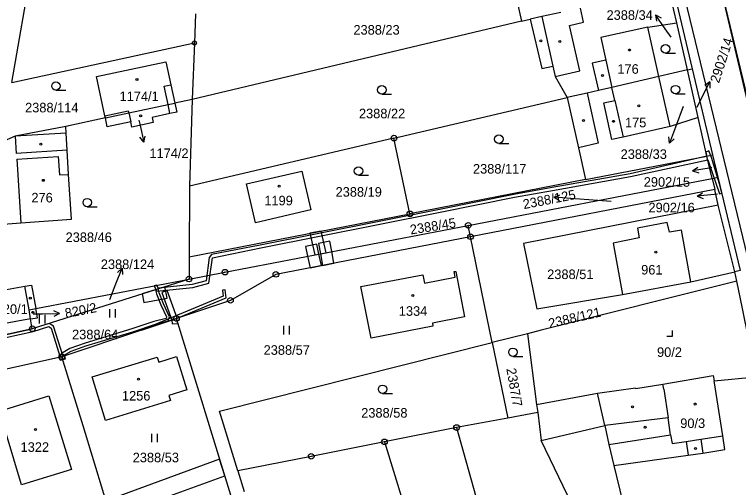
# Model space of a CAD drawing. Extents: x -758836 to -757729, y -1175316 to -1174366.
# Drawn here: x -758454.3 to -758325.7, y -1175111 to -1175027 of the extents above; entities that cross this region are included whole.
import ezdxf

# ---------------------------------------------------------------- set-up
doc = ezdxf.new("R2010")
doc.units = 0
for name, color, linetype in [('Hranice parcel', 7, 'Continuous'), ('Parcelní čísla', 7, 'Continuous'), ('Pop  PČ popisy', 7, 'Continuous'), ('Vnitřní kresba', 7, 'Continuous'), ('Věcná břemena k části', 7, 'Continuous'), ('Značky bodu BP', 7, 'Continuous'), ('Značky budov', 7, 'Continuous'), ('Značky kultur', 7, 'Continuous')]:
    doc.layers.add(name, color=color, linetype=linetype)

msp = doc.modelspace()

# ---------------------------------------------------------------- linework, layer by layer
at = {"layer": 'Hranice parcel'}
for p, q in [((-758367.53, -1175013.58), (-758364.25, -1175028.17)), ((-758336.71, -1175028.44), (-758338.16, -1175021.98)), ((-758422.16, -1175026.87), (-758422.36, -1175032.02)), ((-758364.25, -1175028.17), (-758422.76, -1175042.05)), ((-758364.25, -1175028.17), (-758362.74, -1175027.81)), ((-758334.82, -1175036.8), (-758336.71, -1175028.44)), ((-758454.79, -1175039.02), (-758422.36, -1175032.02)), ((-758422.36, -1175032.02), (-758422.76, -1175042.05)), ((-758334.82, -1175036.8), (-758339.87, -1175037.99)), ((-758334.82, -1175036.8), (-758333.96, -1175036.62)), ((-758332.92, -1175045.26), (-758334.82, -1175036.8)), ((-758333.96, -1175036.62), (-758330.37, -1175051.89)), ((-758422.76, -1175042.05), (-758425.82, -1175042.7)), ((-758422.76, -1175042.05), (-758423.24, -1175057.45)), ((-758386.92, -1175048.94), (-758356.15, -1175041.72)), ((-758438.18, -1175045.35), (-758445.21, -1175046.85)), ((-758331.37, -1175052.13), (-758332.92, -1175045.26)), ((-758386.92, -1175048.94), (-758423.24, -1175057.45)), ((-758384.09, -1175062.4), (-758386.92, -1175048.94)), ((-758352.88, -1175056.32), (-758331.37, -1175052.13)), ((-758331.37, -1175052.13), (-758330.37, -1175051.89)), ((-758330.41, -1175056.09), (-758331.37, -1175052.13)), ((-758330.37, -1175051.89), (-758329.39, -1175055.87)), ((-758352.88, -1175056.32), (-758384.09, -1175062.4)), ((-758330.41, -1175056.09), (-758329.39, -1175055.87)), ((-758330.41, -1175056.09), (-758329.96, -1175058.06)), ((-758329.39, -1175055.87), (-758325.44, -1175072.46)), ((-758423.24, -1175057.45), (-758423.3, -1175070.03)), ((-758329.96, -1175058.06), (-758373.32, -1175066.46)), ((-758329.33, -1175060.85), (-758329.96, -1175058.06)), ((-758326.41, -1175072.69), (-758329.33, -1175060.85)), ((-758423.3, -1175070.03), (-758384.09, -1175062.4)), ((-758373.32, -1175066.46), (-758373.73, -1175064.44)), ((-758373.32, -1175066.46), (-758407.89, -1175073.16)), ((-758369.46, -1175085.29), (-758373.32, -1175066.46)), ((-758423.3, -1175070.03), (-758423.32, -1175073.99)), ((-758334.22, -1175074.5), (-758326.41, -1175072.69)), ((-758325.44, -1175072.46), (-758326.41, -1175072.69)), ((-758326.01, -1175074.36), (-758326.41, -1175072.69)), ((-758423.32, -1175073.99), (-758451.15, -1175082.83)), ((-758450.52, -1175079.23), (-758423.32, -1175073.99)), ((-758346.32, -1175076.76), (-758334.22, -1175074.5)), ((-758451.15, -1175082.83), (-758451.45, -1175081.08)), ((-758415.92, -1175112.41), (-758425.55, -1175080.99)), ((-758363.2, -1175083.72), (-758369.46, -1175085.29)), ((-758363.2, -1175083.72), (-758361.58, -1175096.29)), ((-758369.46, -1175085.29), (-758366.71, -1175098.73)), ((-758445.89, -1175087.81), (-758470.38, -1175093.24)), ((-758330.03, -1175092.1), (-758322.58, -1175091.33)), ((-758361.58, -1175096.29), (-758361.4, -1175097.7)), ((-758366.71, -1175098.73), (-758375.8, -1175100.38)), ((-758361.4, -1175097.7), (-758366.71, -1175098.73)), ((-758361.4, -1175097.7), (-758360.76, -1175102.68)), ((-758375.8, -1175100.38), (-758388.61, -1175102.92)), ((-758375.8, -1175100.38), (-758367.83, -1175129.06)), ((-758349.38, -1175126.44), (-758360.76, -1175102.68)), ((-758388.61, -1175102.92), (-758372.81, -1175154.29)), ((-758414.64, -1175108.08), (-758413.52, -1175111.73))]:
    msp.add_line(p, q, dxfattribs=at)
for points in [[(-758297.14, -1175157.07), (-758301.82, -1175137.17), (-758334.58, -1174998.03), (-758360.35, -1174888.27), (-758361.81, -1174882.07)], [(-758354.19, -1174947.79), (-758350.83, -1174962.63), (-758347.5, -1174977.35), (-758344.08, -1174992.47), (-758340.74, -1175007.26), (-758337.45, -1175021.81), (-758333.96, -1175036.62)], [(-758454.79, -1175039.02), (-758451.2, -1175018.23), (-758447.49, -1174998.37), (-758446.54, -1174994.59)], [(-758357.3, -1175026.59), (-758360.67, -1175027.34), (-758362.74, -1175027.81)], [(-758362.74, -1175027.81), (-758360.65, -1175036.59), (-758358.69, -1175036.15), (-758358.27, -1175038), (-758356.15, -1175041.72)], [(-758339.87, -1175037.99), (-758341.86, -1175029.19), (-758336.71, -1175028.44)], [(-758438.18, -1175045.35), (-758438.27, -1175044.95), (-758439.76, -1175038.01), (-758427.42, -1175035.36), (-758426.52, -1175039.47), (-758425.82, -1175042.7)], [(-758339.87, -1175037.99), (-758348.2, -1175039.91), (-758350.61, -1175040.45), (-758352.63, -1175040.93), (-758356.15, -1175041.72)], [(-758332.92, -1175045.26), (-758337.86, -1175046.85), (-758339.87, -1175037.99)], [(-758356.15, -1175041.72), (-758354.15, -1175050.64), (-758352.88, -1175056.32)], [(-758425.82, -1175042.7), (-758425.48, -1175044.3), (-758426.7, -1175044.56), (-758429.86, -1175045.25), (-758429.67, -1175046.18), (-758433.47, -1175046.99), (-758433.67, -1175046.05), (-758437.83, -1175046.94), (-758438.18, -1175045.35)], [(-758438.18, -1175045.35), (-758434.01, -1175044.46), (-758427.04, -1175042.96), (-758425.82, -1175042.7)], [(-758459.42, -1175064.46), (-758453.17, -1175063.97), (-758444.16, -1175063.35), (-758444.71, -1175055.38), (-758444.96, -1175051.07), (-758445.14, -1175048.05), (-758445.21, -1175046.85)], [(-758445.21, -1175046.85), (-758454.19, -1175048.61), (-758456.63, -1175049.65)], [(-758403.26, -1175054.83), (-758401.68, -1175061.71), (-758411.49, -1175063.99), (-758413.09, -1175057.08), (-758403.26, -1175054.83)], [(-758373.73, -1175064.44), (-758333.2, -1175056.63), (-758330.41, -1175056.09)], [(-758329.33, -1175060.85), (-758363.94, -1175067.64), (-758361.54, -1175079.26), (-758346.32, -1175076.76)], [(-758334.22, -1175074.5), (-758335.85, -1175065.28), (-758338.01, -1175065.68), (-758338.4, -1175063.92), (-758343.65, -1175064.93), (-758343.35, -1175066.68), (-758347.97, -1175067.59), (-758346.32, -1175076.76)], [(-758423.32, -1175073.99), (-758416.94, -1175072.76), (-758373.73, -1175064.44)], [(-758407.89, -1175073.16), (-758415.96, -1175077.77), (-758425.55, -1175080.99)], [(-758381.49, -1175074.69), (-758376.03, -1175073.65), (-758376.21, -1175072.67), (-758375.94, -1175072.63), (-758374.37, -1175080.71), (-758380.1, -1175081.81), (-758380, -1175082.36), (-758390.99, -1175084.49), (-758392.78, -1175075.33), (-758381.78, -1175073.21), (-758381.49, -1175074.69)], [(-758326.01, -1175074.36), (-758360.75, -1175083.1), (-758363.2, -1175083.72)], [(-758322.58, -1175091.33), (-758323.49, -1175086.82), (-758324.78, -1175080.41), (-758325.02, -1175079.25), (-758326.01, -1175074.36)], [(-758451.45, -1175081.08), (-758457.34, -1175082.12), (-758458.39, -1175076.34), (-758452.45, -1175075.26), (-758451.28, -1175075.05), (-758450.52, -1175079.23)], [(-758451.45, -1175081.08), (-758451.73, -1175079.46), (-758450.52, -1175079.23)], [(-758451.45, -1175081.08), (-758450.22, -1175080.86), (-758450.52, -1175079.23)], [(-758425.55, -1175080.99), (-758431.74, -1175083.06), (-758445.89, -1175087.81)], [(-758474.49, -1175088.01), (-758463.5, -1175085.57), (-758451.15, -1175082.83)], [(-758414.64, -1175108.08), (-758417.89, -1175097.49), (-758369.46, -1175085.29)], [(-758436.59, -1175118.23), (-758442.14, -1175100.06), (-758445.89, -1175087.81)], [(-758423.72, -1175093.65), (-758426.88, -1175094.66), (-758426.59, -1175095.6), (-758438.18, -1175099.13), (-758440.54, -1175091.38), (-758428.96, -1175087.86), (-758428.67, -1175088.79), (-758425.56, -1175087.78), (-758423.72, -1175093.65)], [(-758361.58, -1175096.29), (-758350.75, -1175094.27), (-758344, -1175093.3), (-758343.97, -1175093.45), (-758339.15, -1175092.67), (-758330.21, -1175091.16), (-758330.03, -1175092.1)], [(-758347.9, -1175107.11), (-758334.65, -1175105.31), (-758332.05, -1175104.91), (-758328.15, -1175104.31), (-758328.53, -1175101.84), (-758330.03, -1175092.1)], [(-758457.04, -1175097.46), (-758448.22, -1175094.76), (-758444.21, -1175107.85), (-758453.04, -1175110.56), (-758457.04, -1175097.46)], [(-758360.76, -1175102.68), (-758349.48, -1175100.04), (-758348.74, -1175103.39), (-758347.9, -1175107.11)], [(-758388.61, -1175102.92), (-758401.62, -1175105.5), (-758414.64, -1175108.08)], [(-758347.9, -1175107.11), (-758343.08, -1175126.87), (-758339.13, -1175132.41)]]:
    msp.add_lwpolyline(points, dxfattribs=at)
at = {"layer": 'Pop  PČ popisy'}
for p, q in [((-758338.75, -1175029.5), (-758340.47, -1175027.04)), ((-758340.47, -1175027.04), (-758339.49, -1175027.57)), ((-758340.47, -1175027.04), (-758340.31, -1175028.15)), ((-758337.67, -1175031.02), (-758338.75, -1175029.5)), ((-758332.17, -1175041.61), (-758330.81, -1175038.94)), ((-758330.81, -1175038.94), (-758331.71, -1175039.6)), ((-758330.81, -1175038.94), (-758330.82, -1175040.06)), ((-758333.09, -1175043.45), (-758332.17, -1175041.61)), ((-758335.57, -1175043.31), (-758336.94, -1175046.99)), ((-758432.21, -1175045.73), (-758431.99, -1175046.72)), ((-758431.99, -1175046.72), (-758431.37, -1175049.66)), ((-758336.94, -1175046.99), (-758337.97, -1175049.81)), ((-758431.37, -1175049.66), (-758431.08, -1175048.57)), ((-758337.97, -1175049.81), (-758338.09, -1175048.7)), ((-758431.37, -1175049.66), (-758432.06, -1175048.78)), ((-758337.97, -1175049.81), (-758337.15, -1175049.04)), ((-758333.88, -1175054.77), (-758332.98, -1175054.1)), ((-758330.92, -1175054.25), (-758333.88, -1175054.77)), ((-758333.88, -1175054.77), (-758332.8, -1175055.09)), ((-758330.49, -1175054.18), (-758330.92, -1175054.25)), ((-758358.5, -1175059.45), (-758357.47, -1175059.02)), ((-758333.05, -1175059.28), (-758332.1, -1175058.68)), ((-758330.06, -1175058.97), (-758333.05, -1175059.28)), ((-758329.48, -1175058.91), (-758330.06, -1175058.97)), ((-758355.51, -1175059.66), (-758358.5, -1175059.45)), ((-758358.5, -1175059.45), (-758357.54, -1175060.02)), ((-758348.36, -1175060.2), (-758355.51, -1175059.66)), ((-758333.05, -1175059.28), (-758332, -1175059.68)), ((-758436.29, -1175074.86), (-758435.22, -1175072.06)), ((-758435.22, -1175072.06), (-758436.04, -1175072.81)), ((-758435.22, -1175072.06), (-758435.11, -1175073.17)), ((-758437.36, -1175077.62), (-758436.29, -1175074.86)), ((-758446.34, -1175080.1), (-758447.35, -1175079.61)), ((-758451.01, -1175080.18), (-758449.34, -1175080.15)), ((-758449.34, -1175080.15), (-758446.34, -1175080.1)), ((-758446.34, -1175080.1), (-758447.33, -1175080.62))]:
    msp.add_line(p, q, dxfattribs=at)
at = {"layer": 'Vnitřní kresba'}
for p, q in [((-758334.58, -1174998.03), (-758301.51, -1175137.25)), ((-758303.3, -1175156.35), (-758341.2, -1174999.31)), ((-758353.24, -1175028.35), (-758353.81, -1175025.81)), ((-758360.67, -1175027.34), (-758358.69, -1175036.15)), ((-758355.72, -1175028.93), (-758353.24, -1175028.35)), ((-758353.89, -1175036.99), (-758355.72, -1175028.93)), ((-758341.86, -1175029.19), (-758350.2, -1175031.07)), ((-758350.2, -1175031.07), (-758349.3, -1175035.06)), ((-758349.3, -1175035.06), (-758351.71, -1175035.6)), ((-758351.71, -1175035.6), (-758350.61, -1175040.45)), ((-758349.3, -1175035.06), (-758348.2, -1175039.91)), ((-758358.27, -1175038), (-758353.89, -1175036.99)), ((-758427.73, -1175039.73), (-758426.52, -1175039.47)), ((-758427.04, -1175042.96), (-758427.73, -1175039.73)), ((-758352.63, -1175040.93), (-758350.65, -1175049.86)), ((-758347.67, -1175042.23), (-758348.2, -1175039.91)), ((-758349.65, -1175042.68), (-758347.67, -1175042.23)), ((-758347.67, -1175042.23), (-758346.2, -1175048.74)), ((-758426.7, -1175044.56), (-758427.04, -1175042.96)), ((-758348.22, -1175049.2), (-758349.65, -1175042.68)), ((-758438.27, -1175044.95), (-758434.1, -1175044.06)), ((-758434.1, -1175044.06), (-758434.01, -1175044.46)), ((-758434.01, -1175044.46), (-758433.67, -1175046.05)), ((-758337.86, -1175046.85), (-758346.2, -1175048.74)), ((-758445.14, -1175048.05), (-758454.19, -1175048.61)), ((-758454.19, -1175048.61), (-758453.99, -1175051.65)), ((-758346.2, -1175048.74), (-758348.22, -1175049.2)), ((-758350.65, -1175049.86), (-758354.15, -1175050.64)), ((-758444.96, -1175051.07), (-758453.99, -1175051.65)), ((-758453.92, -1175052.67), (-758446.56, -1175052.18)), ((-758446.56, -1175052.18), (-758446.32, -1175055.48)), ((-758453.92, -1175052.67), (-758453.17, -1175063.97)), ((-758446.32, -1175055.48), (-758444.71, -1175055.38)), ((-758451.73, -1175079.46), (-758452.45, -1175075.26)), ((-758339, -1175093.56), (-758339.15, -1175092.67)), ((-758339, -1175093.56), (-758338.23, -1175098.67)), ((-758349.48, -1175100.04), (-758350.75, -1175094.27)), ((-758338.23, -1175098.67), (-758349.48, -1175100.04)), ((-758337.8, -1175101.69), (-758338.23, -1175098.67)), ((-758348.74, -1175103.39), (-758337.8, -1175101.69)), ((-758337.8, -1175101.69), (-758337.54, -1175103.22)), ((-758335.03, -1175102.84), (-758332.43, -1175102.44)), ((-758332.43, -1175102.44), (-758328.53, -1175101.84)), ((-758332.43, -1175102.44), (-758332.05, -1175104.91)), ((-758337.54, -1175103.22), (-758335.03, -1175102.84)), ((-758335.03, -1175102.84), (-758334.65, -1175105.31))]:
    msp.add_line(p, q, dxfattribs=at)
at = {"layer": 'Věcná břemena k části'}
for points in [[(-758329.11, -1175058.81), (-758328.72, -1175058.7), (-758329.1, -1175057.07), (-758330.5, -1175052.36), (-758330.98, -1175051.22), (-758331.52, -1175051.45), (-758331.37, -1175052.13), (-758344.99, -1175055.27), (-758358.85, -1175057.73), (-758365.63, -1175058.95), (-758378.83, -1175061.62), (-758389.83, -1175063.8), (-758410.66, -1175067.95), (-758419.34, -1175069.61), (-758419.76, -1175070.15), (-758420.26, -1175074.32), (-758422.74, -1175074.96), (-758428.77, -1175075.62), (-758429.02, -1175075.09), (-758429.52, -1175075.18), (-758429.07, -1175076.16), (-758422.65, -1175075.46), (-758419.8, -1175074.72), (-758419.16, -1175070.2), (-758410.56, -1175068.44), (-758389.73, -1175064.29), (-758378.73, -1175062.11), (-758365.53, -1175059.45), (-758358.77, -1175058.23), (-758344.89, -1175055.76), (-758331.21, -1175052.8)], [(-758398.95, -1175069.3), (-758399.84, -1175065.46), (-758401.84, -1175065.85), (-758400.96, -1175069.68)], [(-758402.61, -1175068.2), (-758402.25, -1175069.93), (-758401.82, -1175071.98), (-758399.82, -1175071.6), (-758400.25, -1175069.55), (-758400.62, -1175067.78)], [(-758400.33, -1175067.65), (-758399.98, -1175069.49), (-758399.59, -1175071.55), (-758397.58, -1175071.16), (-758397.97, -1175069.11), (-758398.32, -1175067.27)], [(-758446.23, -1175087.88), (-758445.89, -1175087.81), (-758445.64, -1175087.73), (-758445.58, -1175087.55), (-758444.27, -1175086.82), (-758441.63, -1175085.86), (-758433.31, -1175083.34), (-758429.44, -1175082.04), (-758427, -1175081.43), (-758426.79, -1175080.69), (-758427.85, -1175078.39), (-758428.62, -1175076.46), (-758428.81, -1175075.73), (-758429.29, -1175075.89), (-758429.1, -1175076.62), (-758428.31, -1175078.59), (-758427.33, -1175080.73), (-758427.4, -1175081.01), (-758429.58, -1175081.56), (-758433.47, -1175082.86), (-758441.79, -1175085.38), (-758444.47, -1175086.36), (-758445.98, -1175087.21)], [(-758427.21, -1175077.39), (-758427.6, -1175075.35), (-758431.65, -1175076.63), (-758431.35, -1175078.18)], [(-758431.74, -1175083.06), (-758425.55, -1175080.99), (-758416.72, -1175077.32), (-758416.88, -1175075.91), (-758417.38, -1175075.96), (-758417.26, -1175077)], [(-758426.38, -1175081.27), (-758425.55, -1175080.99), (-758425.43, -1175080.95), (-758427.2, -1175076.05), (-758428.14, -1175076.39)], [(-758445.89, -1175087.81), (-758445.64, -1175087.73), (-758447.38, -1175082.35), (-758448.16, -1175081.88), (-758451.15, -1175082.83), (-758455.97, -1175083.9), (-758458.7, -1175084.76), (-758473.92, -1175088.73), (-758474.21, -1175088.81), (-758474.05, -1175089.28), (-758473.59, -1175089.16), (-758458.56, -1175085.24), (-758455.84, -1175084.38), (-758451.02, -1175083.31), (-758448.23, -1175082.43), (-758447.8, -1175082.69), (-758446.23, -1175087.88)], [(-758425.28, -1175081.87), (-758425.55, -1175080.99), (-758426.38, -1175081.27), (-758426.32, -1175081.93)], [(-758445.74, -1175088.29), (-758445.89, -1175087.81), (-758446.38, -1175087.92), (-758446.22, -1175088.43)], [(-758445.74, -1175088.29), (-758445.89, -1175087.81), (-758446.23, -1175087.88), (-758446.38, -1175087.92), (-758446.22, -1175088.43)], [(-758445.64, -1175087.73), (-758445.89, -1175087.81), (-758445.74, -1175088.29), (-758445.27, -1175088.14), (-758445.42, -1175087.65)], [(-758445.64, -1175087.73), (-758445.89, -1175087.81), (-758445.74, -1175088.29), (-758445.27, -1175088.14), (-758445.42, -1175087.65)], [(-758456.92, -1175120.55), (-758455.85, -1175123.36), (-758451.64, -1175121.64), (-758437.17, -1175116.34), (-758416.98, -1175108.94), (-758417.89, -1175105.98), (-758438.06, -1175113.43), (-758452.72, -1175118.84)]]:
    msp.add_lwpolyline(points, close=True, dxfattribs=at)
at = {"layer": 'Značky bodu BP'}
for centre, radius in [((-758422.36, -1175032.02), 0.35), ((-758422.36, -1175032.02), 0.0212), ((-758386.92, -1175048.94), 0.5), ((-758386.92, -1175048.94), 0.0303), ((-758384.09, -1175062.4), 0.5), ((-758384.09, -1175062.4), 0.0303), ((-758373.73, -1175064.44), 0.5), ((-758373.73, -1175064.44), 0.0303), ((-758373.32, -1175066.46), 0.5), ((-758373.32, -1175066.46), 0.0303), ((-758416.94, -1175072.76), 0.5), ((-758416.94, -1175072.76), 0.0303), ((-758407.89, -1175073.16), 0.5), ((-758407.89, -1175073.16), 0.0303), ((-758423.32, -1175073.99), 0.5), ((-758423.32, -1175073.99), 0.0303), ((-758415.96, -1175077.77), 0.5), ((-758415.96, -1175077.77), 0.0303), ((-758425.55, -1175080.99), 0.5), ((-758425.55, -1175080.99), 0.0303), ((-758451.15, -1175082.83), 0.5), ((-758451.15, -1175082.83), 0.0303), ((-758445.89, -1175087.81), 0.5), ((-758445.89, -1175087.81), 0.0303), ((-758375.8, -1175100.38), 0.5), ((-758375.8, -1175100.38), 0.0303), ((-758388.61, -1175102.92), 0.5), ((-758388.61, -1175102.92), 0.0303), ((-758401.62, -1175105.5), 0.5), ((-758401.62, -1175105.5), 0.0303)]:
    msp.add_circle(centre, radius, dxfattribs=at)
at = {"layer": 'Značky budov'}
for centre in [(-758360.84, -1175031.64), (-758357.47, -1175031.78), (-758345.07, -1175033.27), (-758432.56, -1175038.51), (-758349.9, -1175037.81), (-758343.44, -1175043.21), (-758431.91, -1175044.97), (-758353.27, -1175045.81), (-758347.94, -1175045.95), (-758449.63, -1175049.99), (-758449.19, -1175056.44), (-758407.33, -1175057.5), (-758340.42, -1175069.21), (-758383.56, -1175076.93), (-758451.5, -1175077.39), (-758451.06, -1175079.9), (-758432.29, -1175091.78), (-758333.42, -1175096.2), (-758344.57, -1175096.69), (-758342.33, -1175100.34), (-758450.59, -1175100.72), (-758333.35, -1175104.12)]:
    msp.add_circle(centre, 0.175, dxfattribs=at)
at = {"layer": 'Značky kultur'}
for p, q in [((-758338.69, -1175033.81), (-758336.94, -1175033.81)), ((-758446.96, -1175040.42), (-758445.21, -1175040.42)), ((-758389.08, -1175041.1), (-758387.33, -1175041.1)), ((-758336.93, -1175041.06), (-758335.18, -1175041.06)), ((-758368.29, -1175049.88), (-758366.54, -1175049.88)), ((-758393.22, -1175055.53), (-758391.47, -1175055.53)), ((-758441.39, -1175061.15), (-758439.64, -1175061.15)), ((-758437.38, -1175080.84), (-758437.38, -1175079.34)), ((-758436.38, -1175080.84), (-758436.38, -1175079.34)), ((-758449.85, -1175081.87), (-758449.85, -1175080.37)), ((-758448.85, -1175081.87), (-758448.85, -1175080.37)), ((-758406.5, -1175083.83), (-758406.5, -1175082.33)), ((-758405.5, -1175083.83), (-758405.5, -1175082.33)), ((-758337.47, -1175084.13), (-758337.47, -1175083.13)), ((-758338.47, -1175084.13), (-758337.47, -1175084.13)), ((-758365.79, -1175087.75), (-758364.04, -1175087.75)), ((-758388.94, -1175094.33), (-758387.19, -1175094.33)), ((-758429.92, -1175102.99), (-758429.92, -1175101.49)), ((-758428.92, -1175102.99), (-758428.92, -1175101.49))]:
    msp.add_line(p, q, dxfattribs=at)
for centre in [(-758338.69, -1175033.06), (-758446.96, -1175039.67), (-758389.08, -1175040.35), (-758336.93, -1175040.31), (-758368.29, -1175049.13), (-758393.22, -1175054.78), (-758441.39, -1175060.4), (-758365.79, -1175087), (-758388.94, -1175093.58)]:
    msp.add_circle(centre, 0.75, dxfattribs=at)

# ---------------------------------------------------------------- texts
at = {"layer": 'Parcelní čísla'}
for s, p in [('2388/34', (-758349.17, -1175027.91)), ('2388/23', (-758394.12, -1175030.54)), ('176', (-758347.25, -1175037.5)), ('1174/1', (-758435.65, -1175042.35)), ('2388/114', (-758452.43, -1175044.36)), ('2388/22', (-758393.14, -1175045.41)), ('175', (-758345.9, -1175047.02)), ('1174/2', (-758430.35, -1175052.48)), ('2388/33', (-758346.67, -1175052.63)), ('2388/117', (-758372.89, -1175055.24)), ('2902/15', (-758342.56, -1175057.58)), ('2388/19', (-758397.29, -1175059.35)), ('276', (-758451.31, -1175060.37)), ('1199', (-758409.94, -1175060.89)), ('2902/16', (-758341.72, -1175062.13)), ('2388/46', (-758445.24, -1175067.4)), ('2388/124', (-758438.98, -1175072.21)), ('961', (-758343.02, -1175073.18)), ('2388/51', (-758359.71, -1175073.99)), ('820/1', (-758457.65, -1175080.18)), ('1334', (-758386.06, -1175080.52)), ('2388/64', (-758444.09, -1175084.69)), ('2388/57', (-758410.07, -1175087.45)), ('90/2', (-758340.2, -1175087.83)), ('1256', (-758435.23, -1175095.58)), ('2388/58', (-758392.74, -1175098.62)), ('90/3', (-758336.08, -1175100.47)), ('1322', (-758453.23, -1175104.7)), ('2388/53', (-758433.32, -1175106.56))]:
    msp.add_text(s, height=1.7, dxfattribs=at).set_placement(p)
for s, rotation, p in [('2902/14', 72, (-758329.21, -1175039.27)), ('2388/125', 11, (-758363.84, -1175061.56)), ('2388/45', 9, (-758383.93, -1175066.07)), ('820/2', 11, (-758445.19, -1175080.93)), ('2388/121', 13, (-758359.28, -1175082.75)), ('2387/7', 280, (-758366.97, -1175089.95))]:
    msp.add_text(s, height=1.7, rotation=rotation, dxfattribs=at).set_placement(p)

doc.saveas('drawing.dxf')
